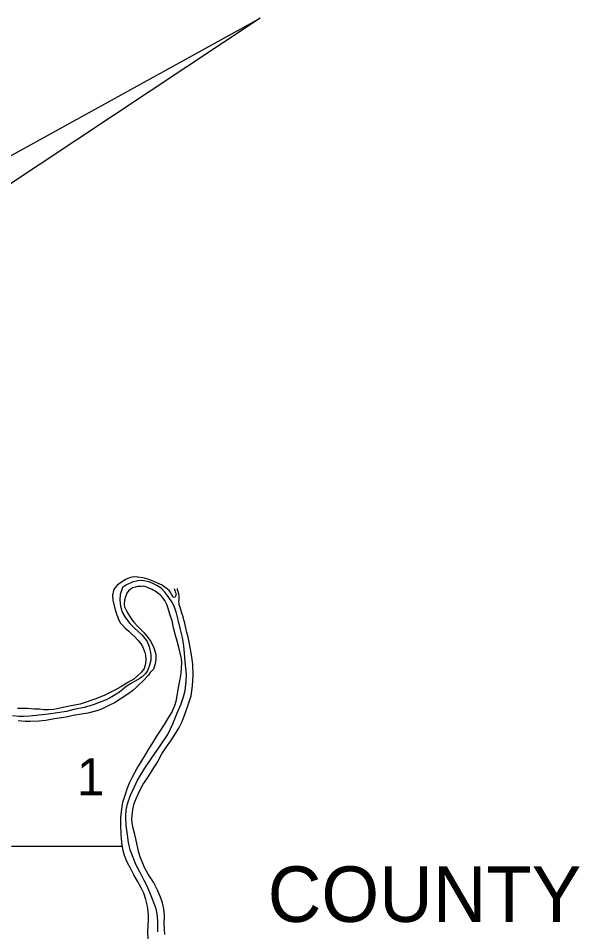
# Model space of a CAD drawing. Extents: x 369523 to 838377, y 495025 to 936819.
# Drawn here: x 696948 to 709756, y 530793 to 551647 of the extents above; entities that cross this region are included whole.
import ezdxf

# ---------------------------------------------------------------- set-up
doc = ezdxf.new("R2010")
doc.units = 0
for name, color, linetype in [('21', 7, 'Continuous'), ('DSN_DRFT_Common-Annotations', 7, 'Continuous'), ('Level 10', 7, 'Continuous'), ('Level 22', 7, 'Continuous'), ('Level 6', 7, 'Continuous')]:
    doc.layers.add(name, color=color, linetype=linetype)

msp = doc.modelspace()

# ---------------------------------------------------------------- linework, layer by layer
at = {"layer": 'DSN_DRFT_Common-Annotations'}
msp.add_lwpolyline([(661941, 529285), (702469, 551647), (663912, 526047)], dxfattribs=at)
at = {"layer": 'Level 10'}
for points in [[(700506, 538632), (700518, 538586), (700528, 538556), (700534, 538538), (700542, 538524), (700548, 538508), (700548, 538502), (700546, 538488), (700544, 538474), (700538, 538456), (700527, 538442), (700517, 538432), (700501, 538426), (700481, 538434), (700463, 538460), (700441, 538502), (700425, 538532), (700387, 538584), (700315, 538648), (700279, 538668), (700227, 538702), (700109, 538756), (700058, 538780), (699988, 538810), (699900, 538844), (699854, 538860), (699788, 538873), (699679, 538889), (699661, 538891), (699601, 538893), (699541, 538889), (699483, 538871), (699393, 538833), (699316, 538781), (699214, 538709), (699172, 538669), (699138, 538625), (699120, 538583), (699100, 538479), (699102, 538362), (699148, 538170), (699180, 538076), (699226, 537948), (699276, 537848), (699322, 537794), (699390, 537726), (699470, 537656), (699542, 537586), (699604, 537524), (699677, 537450), (699721, 537396), (699761, 537344), (699781, 537308), (699813, 537232), (699837, 537170), (699851, 537104), (699855, 537012), (699847, 536912), (699817, 536802), (699758, 536716), (699678, 536646), (699582, 536563), (699449, 536485), (699285, 536387), (699150, 536309), (699014, 536239), (698920, 536192), (698721, 536114), (698601, 536074), (698498, 536036), (698360, 535992), (698230, 535964), (698113, 535942), (697893, 535897), (697760, 535869), (697640, 535859), (697534, 535861), (697429, 535871), (697305, 535877), (697159, 535887), (697034, 535890), (696932, 535886)], [(699909, 530607), (699907, 530795), (699911, 530937), (699921, 531053), (699921, 531191), (699895, 531380), (699859, 531532), (699813, 531672), (699753, 531794), (699665, 531948), (699585, 532094), (699521, 532212), (699421, 532400), (699371, 532534), (699343, 532642), (699311, 532830), (699297, 533024), (699289, 533222), (699285, 533397), (699301, 533539), (699333, 533749), (699392, 533931), (699434, 534059), (699484, 534195), (699552, 534332), (699653, 534512), (699751, 534674), (699833, 534812), (699934, 534974), (700016, 535103), (700112, 535255), (700183, 535369), (700281, 535521), (700363, 535651), (700450, 535800), (700528, 535984), (700558, 536090), (700586, 536276), (700612, 536406), (700641, 536562), (700661, 536699), (700677, 536935), (700671, 537029), (700607, 537285), (700573, 537425), (700537, 537559), (700491, 537733), (700455, 537889), (700405, 538043), (700365, 538175), (700335, 538264), (700291, 538352), (700263, 538396), (700219, 538454), (700185, 538486), (700134, 538526), (700072, 538568), (700026, 538591), (699990, 538613), (699928, 538637), (699840, 538675), (699802, 538679), (699750, 538677), (699675, 538671), (699619, 538661), (699551, 538641), (699523, 538623), (699465, 538575), (699423, 538525), (699406, 538477), (699394, 538439), (699374, 538365), (699364, 538273), (699374, 538207), (699420, 538117), (699452, 538054), (699528, 537926), (699585, 537860), (699675, 537760), (699817, 537620), (699889, 537532), (699973, 537422), (700043, 537272), (700083, 537132), (700089, 537030), (700081, 536938)], [(700288, 530729), (700278, 530976), (700280, 531156), (700268, 531316), (700238, 531452), (700196, 531580), (700122, 531742), (700030, 531922), (699914, 532106), (699838, 532242), (699736, 532484), (699692, 532624), (699636, 532884), (699610, 533015), (699570, 533161), (699548, 533283), (699542, 533367), (699544, 533441), (699562, 533581), (699594, 533723), (699648, 533853), (699718, 534017), (699797, 534160), (699885, 534290), (700006, 534474), (700122, 534664), (700226, 534851), (700329, 535013), (700425, 535149), (700513, 535281), (700608, 535439), (700684, 535592), (700760, 535802), (700835, 535994), (700889, 536176), (700921, 536407), (700941, 536641), (700932, 536899), (700900, 537111), (700862, 537325), (700820, 537519), (700794, 537625), (700764, 537764), (700746, 537834), (700726, 537912), (700706, 537982), (700680, 538064), (700654, 538152), (700632, 538216), (700620, 538258), (700616, 538288), (700612, 538336), (700620, 538368), (700622, 538408), (700618, 538438), (700616, 538458), (700610, 538492), (700608, 538510), (700604, 538532)], [(700604, 538532), (700594, 538566), (700584, 538590), (700582, 538610), (700582, 538632)], [(700081, 536938), (700051, 536836), (700033, 536790), (699959, 536708), (699915, 536648), (699782, 536508), (699700, 536433), (699646, 536375), (699572, 536311), (699525, 536273), (699481, 536239), (699357, 536157), (699269, 536105), (699144, 536019), (699016, 535956), (698843, 535874), (698741, 535834), (698534, 535786), (698394, 535760), (698201, 535729), (698043, 535695), (697772, 535651), (697580, 535615), (697425, 535599), (697217, 535590), (697108, 535594), (696944, 535606)]]:
    msp.add_lwpolyline(points, dxfattribs=at)
at = {"layer": 'Level 22'}
msp.add_lwpolyline([(686036, 532831), (691441, 532780), (696806, 532745), (699301, 532746)], dxfattribs=at)
at = {"layer": 'Level 6'}
for points in [[(700109, 538696), (700032, 538738), (699934, 538780), (699852, 538799), (699758, 538809), (699679, 538803), (699549, 538771), (699415, 538713), (699324, 538649), (699270, 538491), (699264, 538365), (699280, 538222), (699320, 538086), (699394, 537962), (699492, 537832), (699600, 537724), (699757, 537576), (699879, 537436), (699931, 537306), (699973, 537124), (699973, 536994), (699943, 536878), (699895, 536750), (699845, 536682), (699776, 536614), (699704, 536564), (699511, 536455), (699413, 536391), (699261, 536265), (699082, 536159), (698954, 536086), (698655, 535972), (698454, 535910), (698214, 535866), (698047, 535823), (697634, 535761), (697417, 535739), (697201, 535712), (697072, 535704), (696964, 535710), (696816, 535722)], [(700128, 530791), (700128, 531035), (700118, 531200), (700096, 531318), (700026, 531500), (699964, 531654), (699882, 531852), (699819, 531966), (699729, 532142), (699639, 532316), (699567, 532486), (699501, 532666), (699463, 532834), (699437, 533006), (699409, 533215), (699403, 533421), (699413, 533579), (699440, 533717), (699508, 533911), (699588, 534089), (699666, 534256), (699837, 534530), (699992, 534762), (700172, 535011), (700357, 535299), (700476, 535539), (700566, 535770), (700664, 535996), (700719, 536154), (700757, 536304), (700779, 536503), (700783, 536663), (700759, 536955), (700743, 537149), (700727, 537323), (700697, 537511), (700643, 537725), (700603, 537883), (700555, 538064), (700501, 538226), (700449, 538324), (700381, 538426), (700297, 538536), (700205, 538640), (700109, 538696)]]:
    msp.add_lwpolyline(points, dxfattribs=at)

# ---------------------------------------------------------------- texts
at = {"layer": '21'}
msp.add_text('COUNTY', height=1267.2, dxfattribs=at).set_placement((702638, 531018))
at = {"layer": 'Level 22'}
msp.add_text('1', height=845, dxfattribs=at).set_placement((698282, 533910))

doc.saveas('drawing.dxf')
